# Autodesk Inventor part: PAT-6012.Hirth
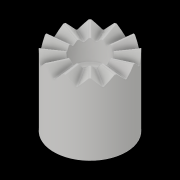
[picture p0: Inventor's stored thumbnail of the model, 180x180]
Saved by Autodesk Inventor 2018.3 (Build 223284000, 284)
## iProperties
Created: 2020-03
Part Number: PAT-6012.Hirth
Material: Generic
Document SubType Name: Modeling
Designer: Th. Mörgeli
Mass: 17.6365 g
Surface Area: 48.3138 cm^2
Volume: 17.6365 cm^3
Density: 1 g/cm^3
Appearance: Default
Author: Th. Mörgeli
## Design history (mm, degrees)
sketch "Sketch2"
  geometry: L1 (-7, 2.028)-(-7, -8); L2 (-7, -8)-(-6, -9); L3 (-6, -9)-(-6, -15); L4 (-6, -15)-(0, -17.184); L5 (0, -17.184)-(0, -28); L6 (0, -28)-(-15, -28); L7 (-15, -28)-(-15, 2.028); L8 (-15, 2.028)-(-7, 2.028); 1 further point
  constraints: 16 end point, 2 parallel, 2 perpendicular, 1 horizontal, 1 point on line, 1 vertical
  dimensions: "d8" = 14 diameter of L1 L5 (= Gewindebohrungsdurchmesser); "d10" = 12 diameter of L3 L5 (= Bohrungsdurchmesser); "d11" = 8 vertical distance of L1.end point (0, 0) (= Gewindetiefe); "d12" = 15 vertical distance of L3.end point (0, 0) (= Bohrungstiefe); "d14" = 45 deg angle of L1 L2; "d15" = 70 deg angle of L5 L4; "d16" = 2.02793 distance from line of point (0, 0) L8 (= 0.5 x Zahnhoehe); "d17" = 30 diameter of L7 L5 (= Aussendurchmesser); "d18" = 28 distance from line of point (0, 0) L6 (= Laenge)
revolve "Grundkoerper" sketch "Sketch2" stored, may be unused: angle "d19" = 90 deg
node "EBENE Aussen"
sketch "SKIZZE Aussen"
  geometry: L1 (-4.056, 2.028)-(0, -2.028); L2 (0, -2.028)-(4.056, 2.028); L3 (4.056, 2.028)-(-4.056, 2.028); L4 (0, 2.028)-(0, -2.028); 2 further points
  constraints: 8 end point, 2 midpoint, 1 coincident, 1 horizontal, 1 perpendicular
  dimensions: "d35" = 90 deg angle of L2 L1 (= Flankenwinkel); "d36" = 4.05586 distance of L4.start L1.end (= Zahnhoehe)
node "EBENE Innen"
sketch "SKIZZE Innen"
  geometry: L1 (-1.014, 0.507)-(0, -0.507); L2 (0, -0.507)-(1.014, 0.507); L3 (1.014, 0.507)-(-1.014, 0.507); L4 (0, 0.507)-(0, -0.507); L5 (-1.014, 0.507)-(-2.535, 2.028); L6 (-2.535, 2.028)-(2.535, 2.028); L7 (2.535, 2.028)-(1.014, 0.507); 3 further points
  constraints: 14 end point, 2 coincident, 2 horizontal, 2 midpoint, 2 perpendicular, 1 collinear
  dimensions: "d38" = 90 deg angle of L2 L1 (= d40); "d39" = 1.01397 distance of L4.start L1.end (= 0.25 x d41); "d44" = 2.02793 distance from line of point (0, 0) L6 (= 0.5 x Zahnhoehe)
feature "Zahnluecke" sketch "SKIZZE Innen" dims "d45" = 0, "d46" = 90 deg, "d47" = 0, "d48" = 90 deg
fillet "Fussradius" dims "d49" = 0.5 (= Fussradius)
pattern_circular "MUSTER Zahn" dims angle "d51" = 360 deg
chamfer "Kopfspiel" distance "d53" = 0.49497 (= 0.707107 x Kopfflaeche); stored, may be unused: second distance "d54" = 2, angle "d55" = 45 deg
body "Solid2"
other parameters: "Aussendurchmesser" = 30 [user parameter; used in 4 equation terms], "Laenge" = 28 [user parameter; used in 1 equation term], "Gewindebohrungsdurchmesser" = 14 [user parameter; used in 1 equation term], "Gewindetiefe" = 8 [user parameter; used in 1 equation term], "Bohrungsdurchmesser" = 12 [user parameter; used in 1 equation term], "Bohrungstiefe" = 15 [user parameter; used in 1 equation term], "Zahnhoehe" = 4.05586 (computed from Aussendurchmesser, Neigungswinkel) [user parameter; used in 3 equation terms], "Neigungswinkel" = 1.34381 [user parameter; used in 1 equation term], "Flankenwinkel" = 90 deg [user parameter; used in 1 equation term], "Fussradius" = 0.5 [user parameter; used in 1 equation term], "Kopfflaeche" = 0.7 [user parameter; used in 1 equation term], "d34" = 15 (= 0.5 x Aussendurchmesser), "d37" = 3.75 (= 0.125 x Aussendurchmesser), "d40" = 90 deg [user parameter; used in 1 equation term], "d41" = 4.05586 (computed from d43, d42) [user parameter; used in 1 equation term], "d42" = 1.34381 [user parameter; used in 1 equation term]
